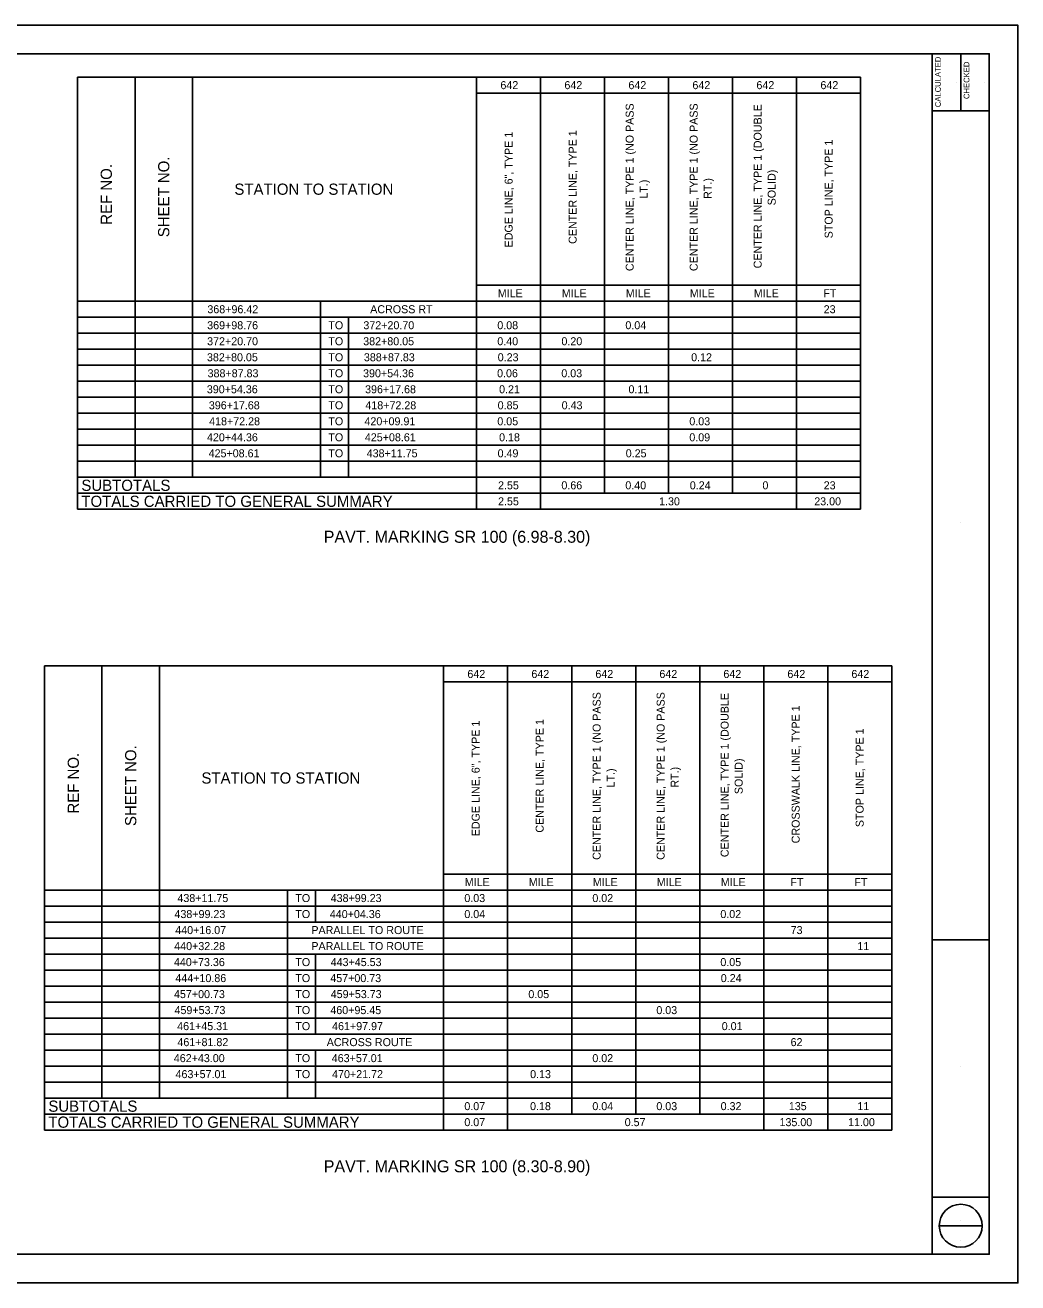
# Model space of a CAD drawing. Extents: x 27.1 to 61.1, y -25.6 to -3.6.
# Drawn here: x 43.76 to 61.13, y -25.57 to -3.57 of the extents above; entities that cross this region are included whole.
import ezdxf

# ---------------------------------------------------------------- set-up
doc = ezdxf.new("R2010")
doc.units = 0
for name, color, linetype in [('SH_Border', 7, 'Continuous'), ('SH_Cut_Line', 7, 'Continuous'), ('SH_Data', 7, 'Continuous'), ('SH_Text', 7, 'Continuous')]:
    doc.layers.add(name, color=color, linetype=linetype)

msp = doc.modelspace()

# ---------------------------------------------------------------- linework, layer by layer
at = {"layer": 'SH_Border'}
for p, q in [((59.633, -25.073), (59.633, -4.073)), ((60.133, -4.073), (60.133, -5.073)), ((59.633, -5.073), (60.633, -5.073)), ((59.633, -19.573), (60.633, -19.573)), ((59.633, -24.073), (60.633, -24.073))]:
    msp.add_line(p, q, dxfattribs=at)
msp.add_lwpolyline([(29.133, -4.073), (60.633, -4.073), (60.633, -25.073), (29.133, -25.073)], close=True, dxfattribs=at)
at = {"layer": 'SH_Cut_Line'}
msp.add_lwpolyline([(27.133, -25.573), (61.133, -25.573), (61.133, -3.573), (27.133, -3.573)], close=True, dxfattribs=at)
at = {"layer": 'SH_Data'}
for p, q in [((44.679, -4.482), (58.382, -4.482)), ((44.679, -4.482), (44.679, -12.042)), ((45.684, -4.482), (45.684, -11.482)), ((46.688, -4.482), (46.688, -11.482)), ((51.662, -4.482), (51.662, -12.042)), ((52.782, -4.482), (52.782, -12.042)), ((53.902, -4.482), (53.902, -11.762)), ((55.022, -4.482), (55.022, -11.762)), ((56.142, -4.482), (56.142, -11.762)), ((57.262, -4.482), (57.262, -12.042)), ((58.382, -4.482), (58.382, -12.042)), ((60.053, -4.569), (60.053, -4.569)), ((60.553, -4.569), (60.553, -4.569)), ((51.662, -4.762), (58.382, -4.762)), ((51.662, -8.122), (58.382, -8.122)), ((44.679, -8.402), (58.382, -8.402)), ((48.928, -8.402), (48.928, -11.482)), ((44.679, -8.682), (58.382, -8.682)), ((49.422, -8.682), (49.422, -11.482)), ((44.679, -8.962), (58.382, -8.962)), ((44.679, -9.242), (58.382, -9.242)), ((44.679, -9.522), (58.382, -9.522)), ((44.679, -9.802), (58.382, -9.802)), ((44.679, -10.082), (58.382, -10.082)), ((44.679, -10.362), (58.382, -10.362)), ((44.679, -10.642), (58.382, -10.642)), ((44.679, -10.922), (58.382, -10.922)), ((44.679, -11.202), (58.382, -11.202)), ((44.679, -11.482), (58.382, -11.482)), ((44.679, -11.762), (58.382, -11.762)), ((44.679, -12.042), (58.382, -12.042)), ((60.133, -12.281), (60.133, -12.281)), ((44.101, -14.782), (58.925, -14.782)), ((44.101, -14.782), (44.101, -22.902)), ((45.106, -14.782), (45.106, -22.342)), ((46.111, -14.782), (46.111, -22.342)), ((51.085, -14.782), (51.085, -22.902)), ((52.205, -14.782), (52.205, -22.902)), ((53.325, -14.782), (53.325, -22.622)), ((54.445, -14.782), (54.445, -22.622)), ((55.565, -14.782), (55.565, -22.622)), ((56.685, -14.782), (56.685, -22.902)), ((57.805, -14.782), (57.805, -22.902)), ((58.925, -14.782), (58.925, -22.902)), ((51.085, -15.062), (58.925, -15.062)), ((51.085, -18.422), (58.925, -18.422)), ((44.101, -18.702), (58.925, -18.702)), ((48.351, -18.702), (48.351, -22.342)), ((48.845, -18.702), (48.845, -19.262)), ((44.101, -18.982), (58.925, -18.982)), ((44.101, -19.262), (58.925, -19.262)), ((44.101, -19.542), (58.925, -19.542)), ((44.101, -19.822), (58.925, -19.822)), ((48.845, -19.822), (48.845, -21.222)), ((44.101, -20.102), (58.925, -20.102)), ((44.101, -20.382), (58.925, -20.382)), ((44.101, -20.662), (58.925, -20.662)), ((44.101, -20.942), (58.925, -20.942)), ((44.101, -21.222), (58.925, -21.222)), ((44.101, -21.502), (58.925, -21.502)), ((48.845, -21.502), (48.845, -22.342)), ((44.101, -21.782), (58.925, -21.782)), ((60.133, -21.781), (60.133, -21.781)), ((44.101, -22.062), (58.925, -22.062)), ((44.101, -22.342), (58.925, -22.342)), ((44.101, -22.622), (58.925, -22.622)), ((44.101, -22.902), (58.925, -22.902)), ((59.758, -24.573), (60.508, -24.573)), ((60.133, -24.488), (60.133, -24.488)), ((60.133, -24.828), (60.133, -24.828))]:
    msp.add_line(p, q, dxfattribs=at)
msp.add_circle((60.133, -24.573), 0.375, dxfattribs=at)

# ---------------------------------------------------------------- texts
for s, p in [('CALCULATED', (59.785, -5.008)), ('CHECKED', (60.285, -4.865))]:
    msp.add_text(s, height=0.1, rotation=90, dxfattribs=at).set_placement(p)
at = {"layer": 'SH_Text'}
for s, height, p in [('642', 0.14, (52.078, -4.692)), ('642', 0.14, (53.198, -4.692)), ('642', 0.14, (54.318, -4.692)), ('642', 0.14, (55.438, -4.692)), ('642', 0.14, (56.558, -4.692)), ('642', 0.14, (57.678, -4.692)), ('STATION TO STATION', 0.196, (47.423, -6.54)), ('MILE', 0.14, (52.032, -8.332)), ('MILE', 0.14, (53.152, -8.332)), ('MILE', 0.14, (54.272, -8.332)), ('MILE', 0.14, (55.392, -8.332)), ('MILE', 0.14, (56.512, -8.332)), ('FT', 0.14, (57.729, -8.332)), ('368+96.42', 0.14, (46.95, -8.612)), ('ACROSS RT', 0.14, (49.799, -8.612)), ('23', 0.14, (57.735, -8.612)), ('369+98.76', 0.14, (46.947, -8.892)), ('TO', 0.14, (49.067, -8.892)), ('372+20.70', 0.14, (49.68, -8.892)), ('0.08', 0.14, (52.024, -8.892)), ('0.04', 0.14, (54.265, -8.892)), ('372+20.70', 0.14, (46.946, -9.172)), ('TO', 0.14, (49.067, -9.172)), ('382+80.05', 0.14, (49.677, -9.172)), ('0.40', 0.14, (52.024, -9.172)), ('0.20', 0.14, (53.146, -9.172)), ('382+80.05', 0.14, (46.943, -9.452)), ('TO', 0.14, (49.067, -9.452)), ('388+87.83', 0.14, (49.689, -9.452)), ('0.23', 0.14, (52.031, -9.452)), ('0.12', 0.14, (55.416, -9.452)), ('388+87.83', 0.14, (46.954, -9.732)), ('TO', 0.14, (49.067, -9.732)), ('390+54.36', 0.14, (49.675, -9.732)), ('0.06', 0.14, (52.02, -9.732)), ('0.03', 0.14, (53.144, -9.732)), ('390+54.36', 0.14, (46.941, -10.012)), ('TO', 0.14, (49.067, -10.012)), ('396+17.68', 0.14, (49.71, -10.012)), ('0.21', 0.14, (52.055, -10.012)), ('0.11', 0.14, (54.319, -10.012)), ('396+17.68', 0.14, (46.976, -10.292)), ('TO', 0.14, (49.067, -10.292)), ('418+72.28', 0.14, (49.715, -10.292)), ('0.85', 0.14, (52.03, -10.292)), ('0.43', 0.14, (53.15, -10.292)), ('418+72.28', 0.14, (46.981, -10.572)), ('TO', 0.14, (49.067, -10.572)), ('420+09.91', 0.14, (49.699, -10.572)), ('0.05', 0.14, (52.024, -10.572)), ('0.03', 0.14, (55.384, -10.572)), ('420+44.36', 0.14, (46.943, -10.852)), ('TO', 0.14, (49.067, -10.852)), ('425+08.61', 0.14, (49.706, -10.852)), ('0.18', 0.14, (52.055, -10.852)), ('0.09', 0.14, (55.384, -10.852)), ('425+08.61', 0.14, (46.972, -11.132)), ('TO', 0.14, (49.067, -11.132)), ('438+11.75', 0.14, (49.738, -11.132)), ('0.49', 0.14, (52.029, -11.132)), ('0.25', 0.14, (54.271, -11.132)), ('SUBTOTALS', 0.196, (44.745, -11.72)), ('2.55', 0.14, (52.037, -11.692)), ('0.66', 0.14, (53.145, -11.692)), ('0.40', 0.14, (54.264, -11.692)), ('0.24', 0.14, (55.392, -11.692)), ('0', 0.14, (56.663, -11.692)), ('23', 0.14, (57.735, -11.692)), ('TOTALS CARRIED TO GENERAL SUMMARY  ', 0.196, (44.745, -12)), ('2.55', 0.14, (52.037, -11.972)), ('1.30', 0.14, (54.855, -11.972)), ('23.00', 0.14, (57.57, -11.972)), ('PAVT. MARKING SR 100 (6.98-8.30)', 0.21, (48.986, -12.627)), ('642', 0.14, (51.5, -14.992)), ('642', 0.14, (52.62, -14.992)), ('642', 0.14, (53.74, -14.992)), ('642', 0.14, (54.86, -14.992)), ('642', 0.14, (55.98, -14.992)), ('642', 0.14, (57.1, -14.992)), ('642', 0.14, (58.22, -14.992)), ('STATION TO STATION', 0.196, (46.846, -16.84)), ('MILE', 0.14, (51.454, -18.632)), ('MILE', 0.14, (52.574, -18.632)), ('MILE', 0.14, (53.694, -18.632)), ('MILE', 0.14, (54.814, -18.632)), ('MILE', 0.14, (55.934, -18.632)), ('FT', 0.14, (57.152, -18.632)), ('FT', 0.14, (58.272, -18.632)), ('438+11.75', 0.14, (46.426, -18.912)), ('TO', 0.14, (48.489, -18.912)), ('438+99.23', 0.14, (49.108, -18.912)), ('0.03', 0.14, (51.447, -18.912)), ('0.02', 0.14, (53.687, -18.912)), ('438+99.23', 0.14, (46.374, -19.192)), ('TO', 0.14, (48.489, -19.192)), ('440+04.36', 0.14, (49.093, -19.192)), ('0.04', 0.14, (51.447, -19.192)), ('0.02', 0.14, (55.927, -19.192)), ('440+16.07', 0.14, (46.388, -19.472)), ('PARALLEL TO ROUTE', 0.14, (48.77, -19.472)), ('73', 0.14, (57.157, -19.472)), ('440+32.28', 0.14, (46.37, -19.752)), ('PARALLEL TO ROUTE', 0.14, (48.77, -19.752)), ('11', 0.14, (58.325, -19.752)), ('440+73.36', 0.14, (46.365, -20.032)), ('TO', 0.14, (48.489, -20.032)), ('443+45.53', 0.14, (49.108, -20.032)), ('0.05', 0.14, (55.927, -20.032)), ('444+10.86', 0.14, (46.39, -20.312)), ('TO', 0.14, (48.489, -20.312)), ('457+00.73', 0.14, (49.101, -20.312)), ('0.24', 0.14, (55.934, -20.312)), ('457+00.73', 0.14, (46.366, -20.592)), ('TO', 0.14, (48.489, -20.592)), ('459+53.73', 0.14, (49.109, -20.592)), ('0.05', 0.14, (52.567, -20.592)), ('459+53.73', 0.14, (46.375, -20.872)), ('TO', 0.14, (48.489, -20.872)), ('460+95.45', 0.14, (49.102, -20.872)), ('0.03', 0.14, (54.807, -20.872)), ('461+45.31', 0.14, (46.422, -21.152)), ('TO', 0.14, (48.489, -21.152)), ('461+97.97', 0.14, (49.133, -21.152)), ('0.01', 0.14, (55.951, -21.152)), ('461+81.82', 0.14, (46.426, -21.432)), ('ACROSS ROUTE', 0.14, (49.039, -21.432)), ('62', 0.14, (57.156, -21.432)), ('462+43.00', 0.14, (46.363, -21.712)), ('TO', 0.14, (48.489, -21.712)), ('463+57.01', 0.14, (49.127, -21.712)), ('0.02', 0.14, (53.687, -21.712)), ('463+57.01', 0.14, (46.393, -21.992)), ('TO', 0.14, (48.489, -21.992)), ('470+21.72', 0.14, (49.133, -21.992)), ('0.13', 0.14, (52.598, -21.992)), ('SUBTOTALS', 0.196, (44.167, -22.58)), ('0.07', 0.14, (51.447, -22.552)), ('0.18', 0.14, (52.597, -22.552)), ('0.04', 0.14, (53.687, -22.552)), ('0.03', 0.14, (54.807, -22.552)), ('0.32', 0.14, (55.932, -22.552)), ('135', 0.14, (57.125, -22.552)), ('11', 0.14, (58.325, -22.552)), ('TOTALS CARRIED TO GENERAL SUMMARY  ', 0.196, (44.167, -22.86)), ('0.07', 0.14, (51.447, -22.832)), ('0.57', 0.14, (54.253, -22.832)), ('135.00', 0.14, (56.962, -22.832)), ('11.00', 0.14, (58.162, -22.832)), ('PAVT. MARKING SR 100 (8.30-8.90)', 0.21, (48.986, -23.639))]:
    msp.add_text(s, height=height, dxfattribs=at).set_placement(p)
for s, height, p in [('CENTER LINE, TYPE 1 (NO PASS', 0.14, (54.41, -7.875)), ('CENTER LINE, TYPE 1 (NO PASS', 0.14, (55.53, -7.875)), ('CENTER LINE, TYPE 1 (DOUBLE', 0.14, (56.65, -7.827)), ('EDGE LINE, 6", TYPE 1', 0.14, (52.292, -7.461)), ('CENTER LINE, TYPE 1', 0.14, (53.412, -7.399)), ('STOP LINE, TYPE 1', 0.14, (57.892, -7.302)), ('SHEET NO.', 0.196, (46.284, -7.283)), ('REF NO.', 0.196, (45.279, -7.065)), ('SOLID)', 0.14, (56.895, -6.725)), ('LT.)', 0.14, (54.655, -6.608)), ('RT.)', 0.14, (55.775, -6.612)), ('CENTER LINE, TYPE 1 (NO PASS', 0.14, (53.832, -18.174)), ('CENTER LINE, TYPE 1 (NO PASS', 0.14, (54.952, -18.174)), ('CENTER LINE, TYPE 1 (DOUBLE', 0.14, (56.072, -18.126)), ('CROSSWALK LINE, TYPE 1', 0.14, (57.315, -17.885)), ('EDGE LINE, 6", TYPE 1', 0.14, (51.715, -17.761)), ('CENTER LINE, TYPE 1', 0.14, (52.835, -17.698)), ('STOP LINE, TYPE 1', 0.14, (58.435, -17.601)), ('SHEET NO.', 0.196, (45.706, -17.582)), ('REF NO.', 0.196, (44.702, -17.364)), ('SOLID)', 0.14, (56.317, -17.024)), ('LT.)', 0.14, (54.077, -16.907)), ('RT.)', 0.14, (55.197, -16.911))]:
    msp.add_text(s, height=height, rotation=90, dxfattribs=at).set_placement(p)

doc.saveas('drawing.dxf')
